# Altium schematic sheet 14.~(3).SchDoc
size 398 x 287 mm
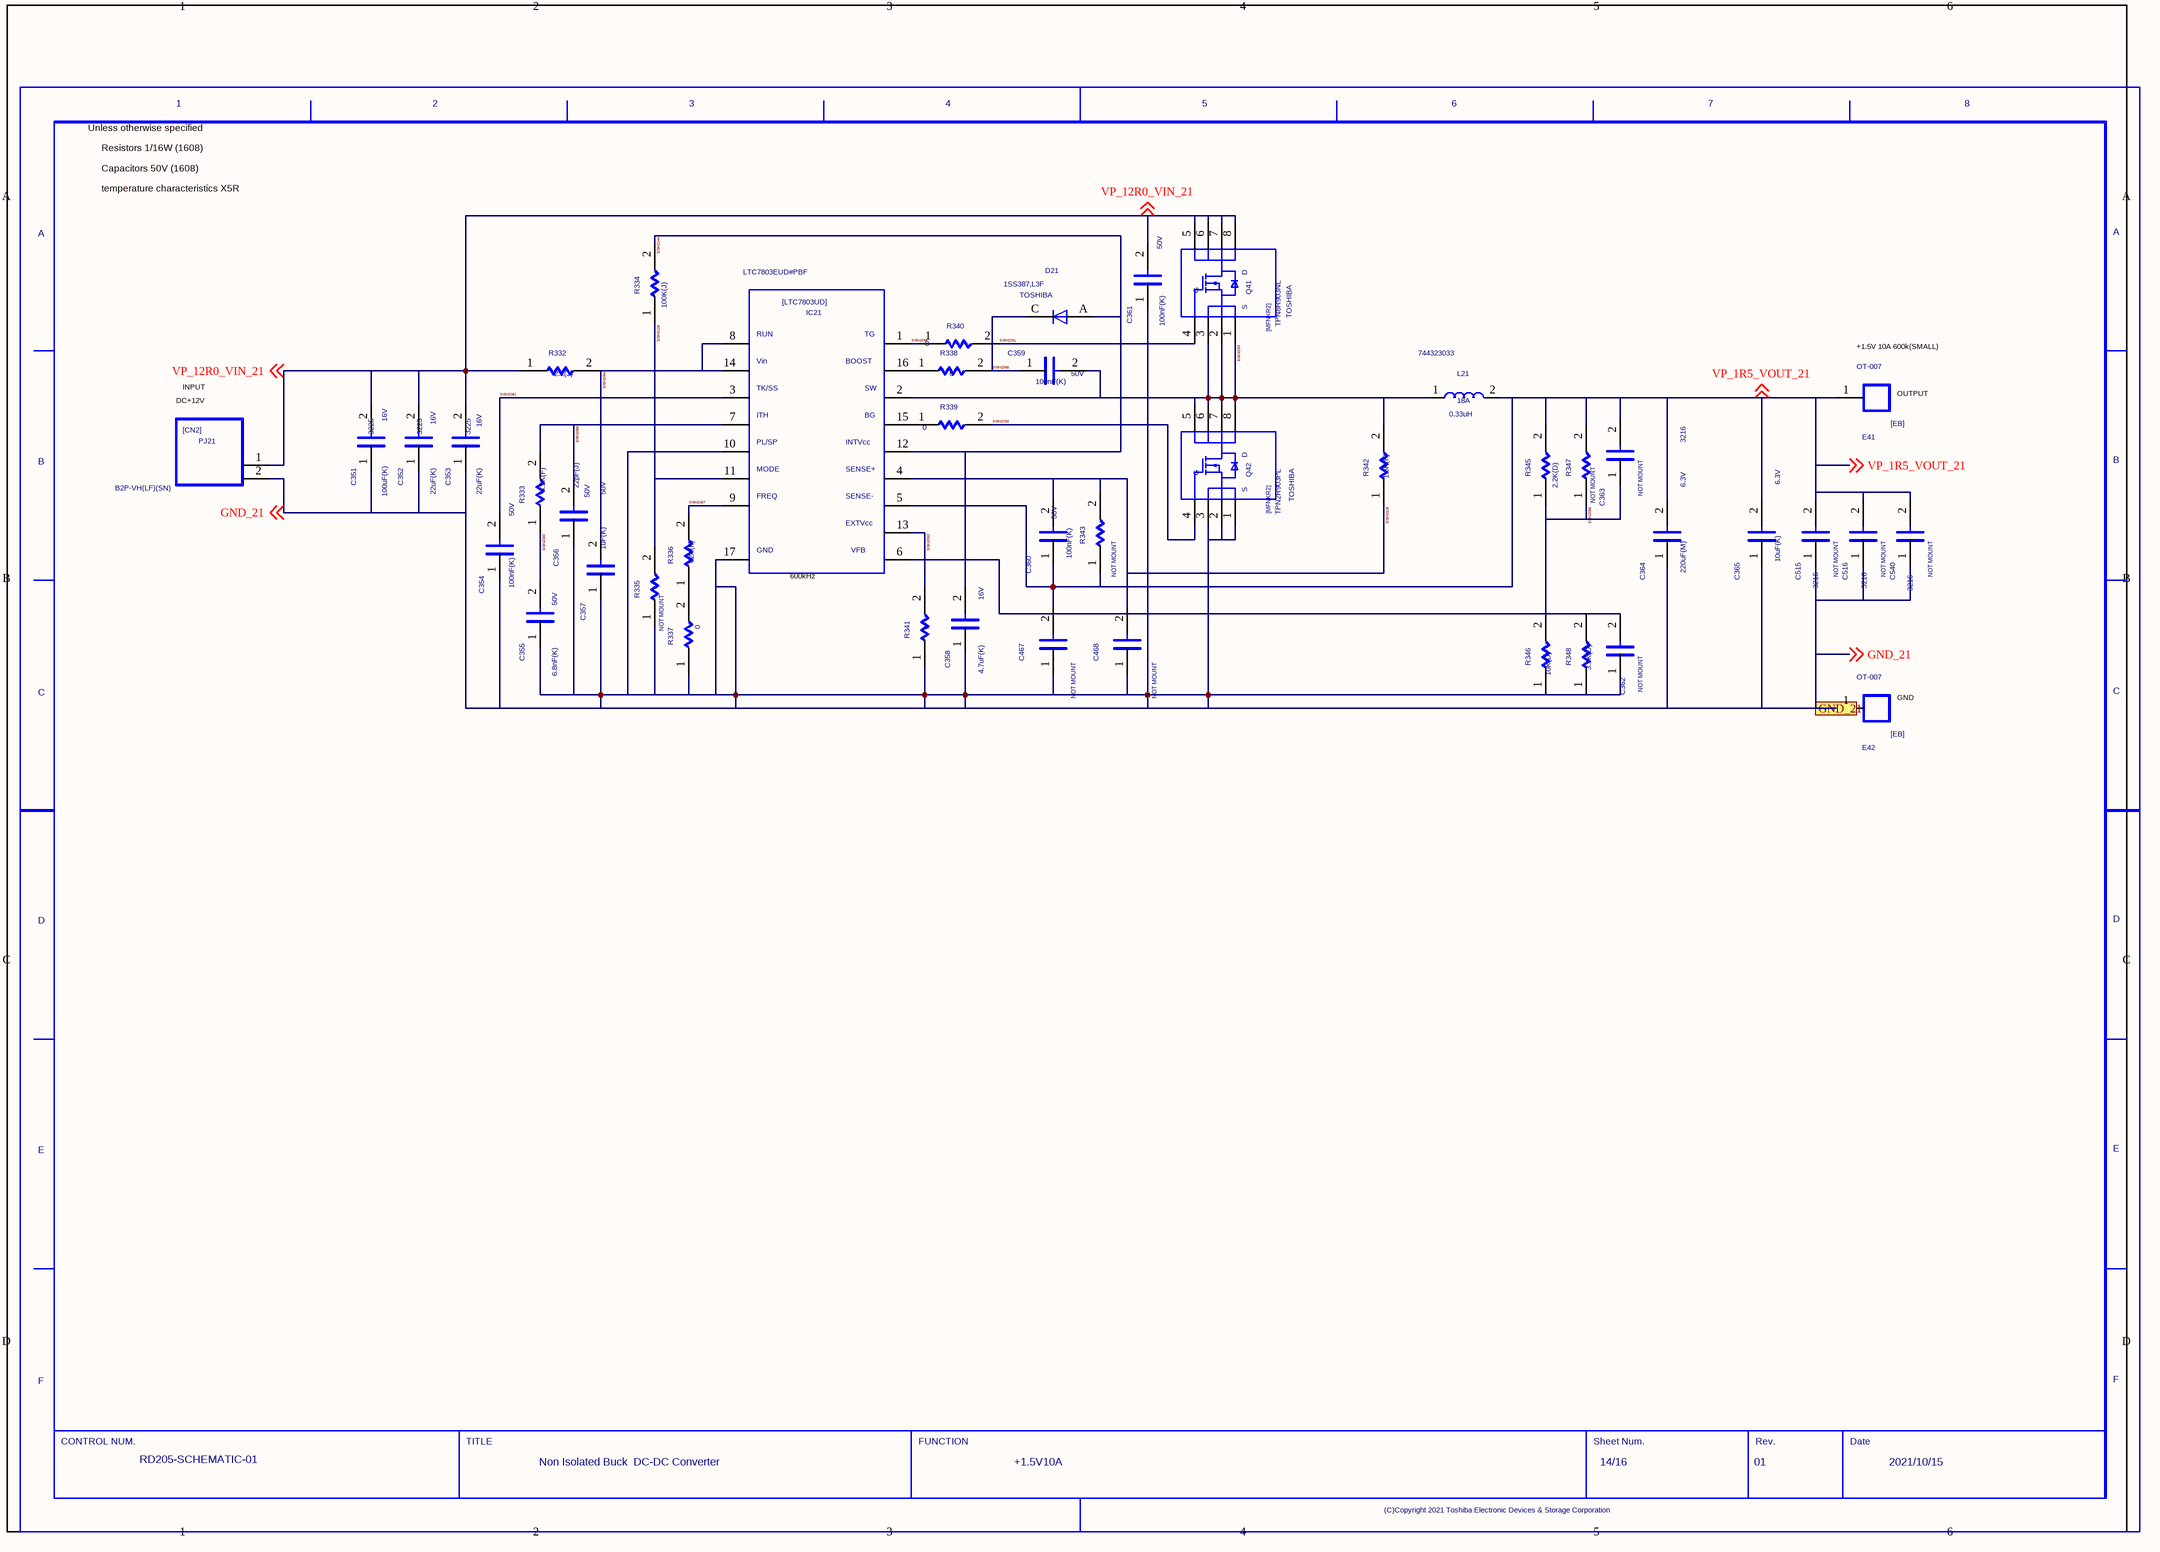
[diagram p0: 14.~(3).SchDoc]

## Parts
C351  SIZECODESMD: 3225  VAL2: 16V  VAL1: 100uF(K)  (hidden comment: C)
C352  SIZECODESMD: 3225  VAL2: 16V  VAL1: 22uF(K)  (hidden comment: C)
C353  SIZECODESMD: 3225  VAL2: 16V  VAL1: 22uF(K)  (hidden comment: C)
C354  VAL2: 50V  VAL1: 100nF(K)  (hidden comment: C)
C355  VAL2: 50V  VAL1: 6.8nF(K)  (hidden comment: C)
C356  VAL2: 50V  VAL1: 22pF(J)  (hidden comment: C)
C357  VAL2: 50V  VAL1: 1uF(K)  (hidden comment: C)
C358  VAL2: 16V  VAL1: 4.7uF(K)  (hidden comment: C)
C359  VAL2: 50V  VAL1: 100nF(K)  (hidden comment: C)
C360  VAL2: 50V  VAL1: 100nF(K)  (hidden comment: C)
C361  VAL2: 50V  VAL1: 100nF(K)  (hidden comment: C)
C362  NOTMOUNT: NOT MOUNT  (hidden comment: C)
C363  NOTMOUNT: NOT MOUNT  (hidden comment: C)
C364  SIZECODESMD: 3216  VAL2: 6.3V  VAL1: 220uF(M)  (hidden comment: C)
C365  VAL2: 6.3V  VAL1: 10uF(K)  (hidden comment: C)
C467  NOTMOUNT: NOT MOUNT  (hidden comment: C)
C468  NOTMOUNT: NOT MOUNT  (hidden comment: C)
C515  NOTMOUNT: NOT MOUNT  SIZECODESMD: 3216  (hidden comment: C)
C516  NOTMOUNT: NOT MOUNT  SIZECODESMD: 3216  (hidden comment: C)
C540  NOTMOUNT: NOT MOUNT  SIZECODESMD: 3216  (hidden comment: C)
D21  USERCOMPTEXT3: TOSHIBA  VAL3: 1SS387,L3F  (hidden comment: D)
E41  VAL3: OT-007  (hidden comment: EB)
E42  VAL3: OT-007  (hidden comment: EB)
IC21  VAL3: LTC7803EUD#PBF  (hidden comment: LTC7803UD)
L21  VAL3: 744323033  VAL2: 18A  VAL1: 0.33uH  (hidden comment: L)
PJ21  VAL3: B2P-VH(LF)(SN)  (hidden comment: CN2)
Q41  USERCOMPTEXT3: TOSHIBA  VAL3: TPN8R903NL  (hidden comment: MFNKR2)
Q42  USERCOMPTEXT3: TOSHIBA  VAL3: TPN2R903PL  (hidden comment: MFNKR2)
R332  VAL1: 2.2(J)  (hidden comment: R)
R333  VAL1: 4.3K(F)  (hidden comment: R)
R334  VAL1: 100K(J)  (hidden comment: R)
R335  NOTMOUNT: NOT MOUNT  (hidden comment: R)
R336  VAL1: 62K(F)  (hidden comment: R)
R337  VAL1: 0  (hidden comment: R)
R338  VAL1: 0  (hidden comment: R)
R339  VAL1: 0  (hidden comment: R)
R340  VAL1: 0  (hidden comment: R)
R341  VAL1: 0  (hidden comment: R)
R342  VAL1: 1.5K(F)  (hidden comment: R)
R343  NOTMOUNT: NOT MOUNT  (hidden comment: R)
R345  VAL1: 2.2K(D)  (hidden comment: R)
R346  VAL1: 10K(D)  (hidden comment: R)
R347  NOTMOUNT: NOT MOUNT  (hidden comment: R)
R348  VAL1: 3.3K(D)  (hidden comment: R)
U?  DATE: 2021/10/15  SHEETNUMBER: 14/16  TITLE: Non Isolated Buck / DC-DC Converter  REVISION: 01  DRAWINGNUMBER: RD205-SCHEMATIC-01  FUNCTION: +1.5V10A  (hidden comment: WAKU_DEF100)

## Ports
GND_21

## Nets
GND_21: C351.1 C352.1 C353.1 C354.1 C355.1 C356.1 C357.1 C358.1 C361.1 C362.1 C364.1 C365.1 C467.1 C468.1 C515.1 C516.1 C540.1 E42.1 IC21.10 IC21.17 PJ21.2 Q42.1 Q42.2 Q42.3 R335.1 R337.1 R341.1 R346.1 R348.1 ; off-sheet GND_21, port GND_21
SIGN2056: C362.2 C363.1 IC21.6 R345.1 R346.2 R347.1 R348.2
SIGN2058: C356.2 IC21.7 R333.2
SIGN2060: C355.2 R333.1
SIGN2061: C354.2 IC21.3
SIGN2063: IC21.13 R341.2
SIGN2064: C357.2 IC21.8 IC21.14 R332.2
SIGN2065: C359.1 D21.C R338.2
SIGN2066: IC21.1 R340.1
SIGN2067: IC21.9 R336.2
SIGN2125: IC21.11 R334.1 R335.2
SIGN2144: C358.2 D21.A IC21.12 R334.2
SIGN2291: Q41.4 R340.2
SIGN2292: Q42.4 R339.2
SIGN2293: C359.2 IC21.2 L21.1 Q41.1 Q41.2 Q41.3 Q42.5 Q42.6 Q42.7 Q42.8 R342.2
SIGN2318: C360.2 C468.2 IC21.4 R342.1 R343.2
VP_1R5_VOUT_21: C360.1 C363.2 C364.2 C365.2 C467.2 C515.2 C516.2 C540.2 E41.1 IC21.5 L21.2 R343.1 R345.2 R347.2 ; off-sheet VP_1R5_VOUT_21
VP_12R0_VIN_21: C351.2 C352.2 C353.2 C361.2 PJ21.1 Q41.5 Q41.6 Q41.7 Q41.8 R332.1 ; off-sheet VP_12R0_VIN_21
NetIC21_15: IC21.15 R339.1
NetIC21_16: IC21.16 R338.1
NetR336_1: R336.1 R337.2

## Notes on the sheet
- Unless otherwise specified
- Capacitors 50V (1608)
- Resistors 1/16W (1608)
- temperature characteristics X5R
- DC+12V
- INPUT
- (near E41) +1.5V 10A 600k(SMALL)
- (near E41) OUTPUT
- (near IC21) 600kHz
- (near E42) GND

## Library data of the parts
C351 = C: SQ_PART_MODEL: CON_100n; FNPARTSNAMEG: CHIP CERAMIC CAPACITOR (3225); USEINPARTSLIST: YES; OriginalSymbolOrigin: (2540,7620); MFSOLDERINGPROP: .; TEMPCHARACTERI2: B; MFFORMINGDIVP: KC; OUMECLASSIFICATION: セラミックコンデンサ; MFMOUNTSYMBOLP: 90; CDMASTERCADCELG: DC903A; PCODE: P03276001115; FNCLASSCODEG: P03-03; MAXGCOUNT: 1; RATEDVOLTAGE: 250; COMPONENTNAME: G36030160049; OUMEMAKER: KYC 京セラ; MFPACKAGEMETHOP: S; NOMINALCAPACITA: 100n; OUMEMAKERKATAMEI: CF32W5R104K250AT; CAPACITANCETOLE: K
C352 C353 = C: SQ_PART_MODEL: CON_22u; FNPARTSNAMEG: CHIP CERAMIC CAPACITOR (3225); USEINPARTSLIST: YES; OriginalSymbolOrigin: (2540,7620); MFSOLDERINGPROP: .; TEMPCHARACTERI2: B; MFFORMINGDIVP: KC; OUMECLASSIFICATION: セラミックコンデンサ; MFMOUNTSYMBOLP: 80; CDMASTERCADCELG: DC903A; PCODE: P03043035626; FNCLASSCODEG: P03-03; MAXGCOUNT: 1; RATEDVOLTAGE: 6.3; COMPONENTNAME: G36030119054; OUMEMAKER: TYD 太陽誘電; MFPACKAGEMETHOP: S; NOMINALCAPACITA: 22u; OUMEMAKERKATAMEI: JMK325BJ226KM-T; CAPACITANCETOLE: K
C354 C359 C361 = C: SQ_PART_MODEL: CON_100n; FNPARTSNAMEG: CHIP CERAMIC CAPACITOR (1608); USEINPARTSLIST: YES; OriginalSymbolOrigin: (2540,7620); MFSOLDERINGPROP: .; TEMPCHARACTERI2: B; MFFORMINGDIVP: KC; OUMECLASSIFICATION: セラミックコンデンサ; SIZECODESMD: 1608; MFMOUNTSYMBOLP: 80; CDMASTERCADCELG: C8100E; PCODE: P03B000000E4; FNCLASSCODEG: P03-03; MAXGCOUNT: 1; RATEDVOLTAGE: 16; COMPONENTNAME: GDM030000598; OUMEMAKER: MRT 村田製作所; MFPACKAGEMETHOP: S; NOMINALCAPACITA: 100n; OUMEMAKERKATAMEI: GRM188B11C104KA01C; CAPACITANCETOLE: K
C355 = C: SQ_PART_MODEL: CON_6.8n; FNPARTSNAMEG: CHIP CERAMIC CAPACITOR (1608); USEINPARTSLIST: YES; OriginalSymbolOrigin: (2540,7620); TOLERANCE: K; ASIMVALUE: 6.8N; MFSOLDERINGPROP: .; TEMPCHARACTERI2: B; MFFORMINGDIVP: KC; OUMECLASSIFICATION: セラミックコンデンサ; SIZECODESMD: 1608; MFMOUNTSYMBOLP: 80; CDMASTERCADCELG: C8100E; PCODE: P03039109225; FNCLASSCODEG: P03-03; MAXGCOUNT: 1; RATEDVOLTAGE: 50; COMPONENTNAME: G36030011440; OUMEMAKER: MRT 村田製作所; MFPACKAGEMETHOP: S; OUMEMAKERKATAMEI: GRM39B682K50PT
C356 = C: SQ_PART_MODEL: CON_22p; FNPARTSNAMEG: CHIP CERAMIC CAPACITOR (1608); USEINPARTSLIST: YES; OriginalSymbolOrigin: (2540,7620); TOLERANCE: J; ASIMVALUE: 22P; CDMASTERCADCELG: C8100E; MFSOLDERINGPROP: .; TEMPCHARACTERI2: CH; MFFORMINGDIVP: KC; OUMECLASSIFICATION: セラミックコンデンサ; SIZECODESMD: 1608; MFMOUNTSYMBOLP: 80; PCODE: P03039A02625; FNCLASSCODEG: P03-03; MAXGCOUNT: 1; RATEDVOLTAGE: 50; COMPONENTNAME: G36030011129; OUMEMAKER: TYD 太陽誘電; MFPACKAGEMETHOP: S; OUMEMAKERKATAMEI: UMK107CH220JZ-T
C357 = C: SQ_PART_MODEL: CON_1u; FNPARTSNAMEG: CHIP CERAMIC CAPACITOR (1608); USEINPARTSLIST: YES; OriginalSymbolOrigin: (2540,7620); MFSOLDERINGPROP: .; TEMPCHARACTERI2: B; MFFORMINGDIVP: KC; OUMECLASSIFICATION: セラミックコンデンサ; SIZECODESMD: 1608; MFMOUNTSYMBOLP: 80; CDMASTERCADCELG: C8100E; PCODE: P03039ACE122; FNCLASSCODEG: P03-03; MAXGCOUNT: 1; RATEDVOLTAGE: 6.3; COMPONENTNAME: G36030104159; OUMEMAKER: KYC 京セラ; MFPACKAGEMETHOP: S; NOMINALCAPACITA: 1u; OUMEMAKERKATAMEI: CM105B105K06ATN; CAPACITANCETOLE: K
C358 = C: SQ_PART_MODEL: CON_4.7u; FNPARTSNAMEG: CHIP CERAMIC CAPACITOR (1608); USEINPARTSLIST: YES; OriginalSymbolOrigin: (2540,7620); MFSOLDERINGPROP: .; TEMPCHARACTERI2: B; MFFORMINGDIVP: KC; OUMECLASSIFICATION: セラミックコンデンサ; SIZECODESMD: 1608; MFMOUNTSYMBOLP: 80; CDMASTERCADCELG: C8100E; PCODE: P03B000000MS; FNCLASSCODEG: P03-03; MAXGCOUNT: 1; RATEDVOLTAGE: 4; COMPONENTNAME: GDM030000053; OUMEMAKER: KYC 京セラ; MFPACKAGEMETHOP: S; NOMINALCAPACITA: 4.7u; OUMEMAKERKATAMEI: CM105B475M04AT; CAPACITANCETOLE: M
C360 = C: SQ_PART_MODEL: CON_100n; FNPARTSNAMEG: CHIP CERAMIC CAPACITOR (1608); USEINPARTSLIST: YES; OriginalSymbolOrigin: (2540,7620); MFSOLDERINGPROP: .; TEMPCHARACTERI2: B; MFFORMINGDIVP: KC; OUMECLASSIFICATION: セラミックコンデンサ; SIZECODESMD: 1608; MFMOUNTSYMBOLP: 80; CDMASTERCADCELG: C8100E; PCODE: P03B000000E4; FNCLASSCODEG: P03-03; MAXGCOUNT: 1; RATEDVOLTAGE: 16; COMPONENTNAME: GDM030001129; OUMEMAKER: MRT 村田製作所; MFPACKAGEMETHOP: S; NOMINALCAPACITA: 100n; OUMEMAKERKATAMEI: GRM188B11C104KA01C; CAPACITANCETOLE: K
C362 C363 = C: SQ_PART_MODEL: CON_100p; FNPARTSNAMEG: CHIP CERAMIC CAPACITOR (1608); USEINPARTSLIST: YES; OriginalSymbolOrigin: (2540,7620); TOLERANCE: J; ASIMVALUE: 100P; MFSOLDERINGPROP: .; TEMPCHARACTERI2: CH; MFFORMINGDIVP: KC; OUMECLASSIFICATION: セラミックコンデンサ; SIZECODESMD: 1608; MFMOUNTSYMBOLP: 80; CDMASTERCADCELG: C8100E; PCODE: P03039177125; FNCLASSCODEG: P03-03; MAXGCOUNT: 1; RATEDVOLTAGE: 50; COMPONENTNAME: G36030011365; OUMEMAKER: KYC 京セラ; MFPACKAGEMETHOP: S; OUMEMAKERKATAMEI: CM105CH101J50AT; VAL2: 50V; VAL1: 100pF(J)
C364 = C: SQ_PART_MODEL: CON_22u; FNPARTSNAMEG: CHIP CERAMIC CAPACITOR (3216); USEINPARTSLIST: YES; OriginalSymbolOrigin: (2540,7620); MFSOLDERINGPROP: .; TEMPCHARACTERI2: B; MFFORMINGDIVP: KC; OUMECLASSIFICATION: セラミックコンデンサ; MFMOUNTSYMBOLP: 80; CDMASTERCADCELG: DC901A; PCODE: P03B0000004V; FNCLASSCODEG: P03-03; MAXGCOUNT: 1; RATEDVOLTAGE: 6.3; COMPONENTNAME: GDM030000020; OUMEMAKER: KYC 京セラ; MFPACKAGEMETHOP: S; NOMINALCAPACITA: 22u; OUMEMAKERKATAMEI: CM316B226M06AT; CAPACITANCETOLE: M
C365 = C: SQ_PART_MODEL: CON_1u; FNPARTSNAMEG: CHIP CERAMIC CAPACITOR (1608); PARTCOMMENT: 代表セル<KC0008> がフットプリントに登録されていません。; USEINPARTSLIST: YES; OriginalSymbolOrigin: (2540,7620); MFSOLDERINGPROP: .; TEMPCHARACTERI2: B; MFPACKAGEMETHOP: S; MFFORMINGDIVP: KC; MFMOUNTSYMBOLP: 80; PCODE: P03B000000ZQ; OUMECLASSIFICATION: セラミックコンデンサ; SIZECODESMD: 1608; CDMASTERCADCELG: KC0008; FNCLASSCODEG: P03-03; MAXGCOUNT: 1; RATEDVOLTAGE: 6.3; COMPONENTNAME: GDM030000202; OUMEMAKER: MRT 村田製作所; NOMINALCAPACITA: 1u; OUMEMAKERKATAMEI: GRM185B10J105KE21D; CAPACITANCETOLE: K
C467 C468 = C: SQ_PART_MODEL: CON_220n; FNPARTSNAMEG: CHIP CERAMIC CAPACITOR (1608); PARTCOMMENT: 代表セル<KC0008> がフットプリントに登録されていません。; USEINPARTSLIST: YES; OriginalSymbolOrigin: (2540,7620); MFSOLDERINGPROP: .; TEMPCHARACTERI2: B; MFFORMINGDIVP: KC; OUMECLASSIFICATION: セラミックコンデンサ; SIZECODESMD: 1608; MFMOUNTSYMBOLP: 80; CDMASTERCADCELG: KC0008; PCODE: P03B000001L3; FNCLASSCODEG: P03-03; MAXGCOUNT: 1; RATEDVOLTAGE: 16; COMPONENTNAME: GDM030001129; OUMEMAKER: MRT 村田製作所; MFPACKAGEMETHOP: S; NOMINALCAPACITA: 220n; OUMEMAKERKATAMEI: GRM188B11C224KA01D; VAL2: 16V; VAL1: 220nF(K); CAPACITANCETOLE: K
C515 C516 C540 = C: SQ_PART_MODEL: CON_22u; FNPARTSNAMEG: CHIP CERAMIC CAPACITOR (3216); USEINPARTSLIST: YES; OriginalSymbolOrigin: (2540,7620); MFSOLDERINGPROP: .; TEMPCHARACTERI2: B; MFFORMINGDIVP: KC; OUMECLASSIFICATION: セラミックコンデンサ; MFMOUNTSYMBOLP: 80; CDMASTERCADCELG: DC901A; PCODE: P03B0000004V; FNCLASSCODEG: P03-03; MAXGCOUNT: 1; RATEDVOLTAGE: 6.3; COMPONENTNAME: GDM030000020; OUMEMAKER: KYC 京セラ; MFPACKAGEMETHOP: S; NOMINALCAPACITA: 22u; OUMEMAKERKATAMEI: CM316B226M06AT; VAL2: 6.3V; VAL1: 22uF(M); CAPACITANCETOLE: M
D21 = D: FNPARTSNAMEG: DIODE; USEINPARTSLIST: YES; PARTNAME: GDM420000143; SAVEAREA0: -565,-171,12979,8058; SAVECOUNT: 1; TIME: 14:49:55; UPDATEUSER: 19870035; UPDATETIME: 14:20:16; OriginalSymbolOrigin: (5080,5080); FORWARDVOLTAGEM: 0; MAXREVERSEVOLTA: 80; COMPONENTNAME: GDM420000143_package; MFSOLDERINGPROP: .; OUMEMAKER: TSB 東芝（ＹＰＳＳ）; QUADMODEL: dummymodel; MFPACKAGEMETHOP: S; MFFORMINGDIVP: MM; MOUNTINGFORMSMD: SMD; OUMECLASSIFICATION: 小信号ダイオード; OUMEMAKERKATAMEI: 1SS387(TPH3,F); CDMASTERCADCELG: D8101D; PCODE: P42B0000008E; FNCLASSCODEG: P42-01
E41 E42 = EB: FNPARTSNAMEG: TERMINAL; USEINPARTSLIST: YES; PARTNAME: 5P9L1232P001; OUMEPARTTYPE: TB; OriginalSymbolOrigin: (2540,12700); COMPONENTNAME: 5P9L1232P001_package; MAXGCOUNT: 1; MFSOLDERINGPROP: .; OUMEMAKER: オサダ; QUADMODEL: dummymodel; MFPACKAGEMETHOP: I; MFFORMINGDIVP: OD; OUMECLASSIFICATION: 端子台、端子板; CDMASTERCADCELG: DE0009; KIND: PBS; PCODE: P29045001117; TERMINALSTYLE: SC; FNCLASSCODEG: P29-01
IC21 = LTC7803UD: USEINPARTSLIST: YES; SAVECOUNT: 29; SAVEAREA0: -53177,0,89020,58420; TIME: 16:14:14; UPDATEUSER: q91866sr; UPDATETIME: 13:15:36; OriginalSymbolOrigin: (5080,55880); MAXGCOUNT: 1; COMPONENTNAME: LTC7803UD_LTC7803UD; OUMEMAKER: ANALOG DEVICES
L21 = L: USEINPARTSLIST: YES; PARTNAME: 7443310047; OriginalSymbolOrigin: (2540,5080); MAXGCOUNT: 1; COMPONENTNAME: L_L; OUMEMAKER: WURTH
PJ21 = CN2: FNPARTSNAMEG: 3.96PITCH NYLON CONNECTOR; USEINPARTSLIST: YES; PARTNAME: G36220114012; OUMEPARTTYPE: CN; OriginalSymbolOrigin: (2540,15240); MAXGCOUNT: 1; RATEDCURRENT: 7; COMPONENTNAME: G36220114012_package; MFSOLDERINGPROP: .; OUMEMAKER: JST 日本圧着端子製造; NUMBEROFCONTACT: 2; QUADMODEL: dummymodel; MFPACKAGEMETHOP: I; MFFORMINGDIVP: CU; CONTACTPITCH: 3.96m; OUMEMAKERKATAMEI: B2P-VH; CDMASTERCADCELG: DPJ514; PCODE: P22346001114; TERMINALSTYLE: PW; FNCLASSCODEG: P22-10
Q41 Q42 = MFNKR2: USEINPARTSLIST: YES; PARTNAME: TPN1R603PL; SAVEAREA0: -9199,-39,32138,22820; TIME: 18:57:44; UPDATEUSER: q91866sr; UPDATETIME: 12:36:02; SAVECOUNT: 10; OriginalSymbolOrigin: (5080,20320); MAXGCOUNT: 1; COMPONENTNAME: MFNKR2_MFNKR2
R332 = R: SQ_PART_MODEL: RES_2.2; FNPARTSNAMEG: CHIP RESISTOR (1608); USEINPARTSLIST: YES; OriginalSymbolOrigin: (5080,5080); TOLERANCE: J; ASIMVALUE: 2.2; MAXGCOUNT: 1; COMPONENTNAME: G36010011507; MFSOLDERINGPROP: .; OUMEMAKER: NAE 松下電子部品; MFPACKAGEMETHOP: S; MFFORMINGDIVP: KC; MOUNTINGFORMSMD: SMD; OUMECLASSIFICATION: 表面実装用固定抵抗器; MFMOUNTSYMBOLP: 80; POWERRATING: 63m; OUMEMAKERKATAMEI: ERJ3GEYJ2R2V; NUMBEROFELEMENT: 0; VAL2: 62.5mW; CDMASTERCADCELG: DR802R; PCODE: P01042157622; FNCLASSCODEG: P01-08
R333 = R: SQ_PART_MODEL: RES_4.3K; FNPARTSNAMEG: CHIP RESISTOR (1608); USEINPARTSLIST: YES; OriginalSymbolOrigin: (5080,5080); PCODE: P01042335624; MAXGCOUNT: 1; COMPONENTNAME: G5101105L102; MFSOLDERINGPROP: .; OUMEMAKER: NAE 松下電子部品; MFPACKAGEMETHOP: S; MFFORMINGDIVP: KC; MOUNTINGFORMSMD: SMD; OUMECLASSIFICATION: 表面実装用固定抵抗器; RESISTANCETOLER: F; MFMOUNTSYMBOLP: 80; POWERRATING: 63m; OUMEMAKERKATAMEI: ERJ3GEYF432V; NOMINALRESISTAN: 4.3K; NUMBEROFELEMENT: 0; VAL2: 62.5mW; CDMASTERCADCELG: DR802R; FNCLASSCODEG: P01-08
R334 = R: SQ_PART_MODEL: RES_100K; FNPARTSNAMEG: CHIP RESISTOR (1608); USEINPARTSLIST: YES; OriginalSymbolOrigin: (5080,5080); TOLERANCE: J; ASIMVALUE: 100K; MFSOLDERINGPROP: .; MFPACKAGEMETHOP: S; MFFORMINGDIVP: KC; MOUNTINGFORMSMD: SMD; MFMOUNTSYMBOLP: 80; NUMBEROFELEMENT: 0; PCODE: P01042047220; MAXGCOUNT: 1; COMPONENTNAME: G36010011057; OUMEMAKER: HDK 北陸電気工業; OUMECLASSIFICATION: 表面実装用固定抵抗器; POWERRATING: 63m; OUMEMAKERKATAMEI: CR1/16 104JV; VAL2: 62.5mW; CDMASTERCADCELG: DR802R; FNCLASSCODEG: P01-08
R335 = R: SQ_PART_MODEL: RES_10; FNPARTSNAMEG: CHIP RESISTOR (1608); USEINPARTSLIST: YES; OriginalSymbolOrigin: (5080,5080); TOLERANCE: F; ASIMVALUE: 10; MFSOLDERINGPROP: .; MFPACKAGEMETHOP: S; MFFORMINGDIVP: KC; MOUNTINGFORMSMD: SMD; MFMOUNTSYMBOLP: 80; NUMBEROFELEMENT: 0; PCODE: P01042036620; MAXGCOUNT: 1; COMPONENTNAME: G36010104063; OUMEMAKER: NAE 松下電子部品; OUMECLASSIFICATION: 表面実装用固定抵抗器; POWERRATING: 63m; OUMEMAKERKATAMEI: ERJ3GEYF100V; VAL2: 62.5mW; VAL1: 10(F); CDMASTERCADCELG: DR802R; FNCLASSCODEG: P01-08
R336 = R: SQ_PART_MODEL: RES_62K; FNPARTSNAMEG: CHIP RESISTOR (1608); USEINPARTSLIST: YES; OriginalSymbolOrigin: (5080,5080); MAXGCOUNT: 1; COMPONENTNAME: GDM010001037; MFSOLDERINGPROP: .; OUMEMAKER: NAE 松下電子部品; MFPACKAGEMETHOP: S; MFFORMINGDIVP: KC; MOUNTINGFORMSMD: SMD; OUMECLASSIFICATION: 表面実装用固定抵抗器; RESISTANCETOLER: F; MFMOUNTSYMBOLP: 80; POWERRATING: 63m; OUMEMAKERKATAMEI: ERJ3GEYF623V; NOMINALRESISTAN: 62K; NUMBEROFELEMENT: 0; VAL2: 62.5mW; CDMASTERCADCELG: DR802R; PCODE: P01042441622; FNCLASSCODEG: P01-08
R337 = R: SQ_PART_MODEL: RES_160K; FNPARTSNAMEG: CHIP RESISTOR (1608); USEINPARTSLIST: YES; OriginalSymbolOrigin: (5080,5080); MAXGCOUNT: 1; COMPONENTNAME: G51011061108; MFSOLDERINGPROP: .; OUMEMAKER: HDK 北陸電気工業; MFPACKAGEMETHOP: S; MFFORMINGDIVP: KC; MOUNTINGFORMSMD: SMD; OUMECLASSIFICATION: 表面実装用固定抵抗器; RESISTANCETOLER: F; MFMOUNTSYMBOLP: 80; POWERRATING: 63m; OUMEMAKERKATAMEI: CR1/16 164FV; NOMINALRESISTAN: 160K; VAL2: 62.5mW; CDMASTERCADCELG: DR802R; PCODE: P01042125225; FNCLASSCODEG: P01-08
R338 R341 = R: SQ_PART_MODEL: RES_10; FNPARTSNAMEG: CHIP RESISTOR (1608); USEINPARTSLIST: YES; OriginalSymbolOrigin: (5080,5080); TOLERANCE: F; ASIMVALUE: 10; MFSOLDERINGPROP: .; MFPACKAGEMETHOP: S; MFFORMINGDIVP: KC; MOUNTINGFORMSMD: SMD; MFMOUNTSYMBOLP: 80; PCODE: P01042036620; MAXGCOUNT: 1; COMPONENTNAME: G36010104063; OUMEMAKER: NAE 松下電子部品; OUMECLASSIFICATION: 表面実装用固定抵抗器; POWERRATING: 63m; OUMEMAKERKATAMEI: ERJ3GEYF100V; VAL2: 62.5mW; CDMASTERCADCELG: DR802R; FNCLASSCODEG: P01-08
R339 R340 = R: SQ_PART_MODEL: RES_10; FNPARTSNAMEG: CHIP RESISTOR (2012); USEINPARTSLIST: YES; OriginalSymbolOrigin: (5080,5080); MAXGCOUNT: 1; TOLERANCE: F; COMPONENTNAME: 5P9L1083P100; MFSOLDERINGPROP: .; OUMEMAKER: 北陸電気工業; MFPACKAGEMETHOP: S; MFFORMINGDIVP: KC; MOUNTINGFORMSMD: SMD; OUMECLASSIFICATION: 表面実装用固定抵抗器; ASIMVALUE: 10; MFMOUNTSYMBOLP: 90; POWERRATING: 100m; OUMEMAKERKATAMEI: CR1/10 100FV Pb(F); VAL2: 125mW; CDMASTERCADCELG: DR910A; PCODE: P01043091222; FNCLASSCODEG: P01-08
R342 = R: SQ_PART_MODEL: RES_1.5K; FNPARTSNAMEG: CHIP RESISTOR (1608); USEINPARTSLIST: YES; OriginalSymbolOrigin: (5080,5080); TOLERANCE: F; ASIMVALUE: 1.5K; MAXGCOUNT: 1; COMPONENTNAME: G36010104407; MFSOLDERINGPROP: .; OUMEMAKER: HDK 北陸電気工業; MFPACKAGEMETHOP: S; MFFORMINGDIVP: KC; MOUNTINGFORMSMD: SMD; OUMECLASSIFICATION: 表面実装用固定抵抗器; MFMOUNTSYMBOLP: 80; POWERRATING: 63m; OUMEMAKERKATAMEI: CR1/16 152FV; NUMBEROFELEMENT: 0; VAL2: 62.5mW; CDMASTERCADCELG: DR802R; PCODE: P01042512223; FNCLASSCODEG: P01-08
R343 = R: SQ_PART_MODEL: RES_8.2K; FNPARTSNAMEG: CHIP RESISTOR (1608); USEINPARTSLIST: YES; OriginalSymbolOrigin: (5080,5080); TOLERANCE: F; ASIMVALUE: 8.2K; MAXGCOUNT: 1; COMPONENTNAME: G36010027188; OUMEMAKER: KAM 釜屋電機; MOUNTINGFORMSMD: SMD; OUMECLASSIFICATION: 表面実装用固定抵抗器; POWERRATING: 63m; OUMEMAKERKATAMEI: RMC1/16-822FTP; CDMASTERCADCELG: DR802R; MFSOLDERINGPROP: .; MFPACKAGEMETHOP: S; MFFORMINGDIVP: KC; MFMOUNTSYMBOLP: 80; NUMBEROFELEMENT: 0; VAL2: 62.5mW; VAL1: 8.2K(F); PCODE: P01042507328; FNCLASSCODEG: P01-08
R345 = R: SQ_PART_MODEL: RES_2.2K; FNPARTSNAMEG: CHIP RESISTOR (1608); USEINPARTSLIST: YES; OriginalSymbolOrigin: (5080,5080); MAXGCOUNT: 1; COMPONENTNAME: G36010129332; MFSOLDERINGPROP: .; OUMEMAKER: NAE 松下電子部品; MFPACKAGEMETHOP: S; MFFORMINGDIVP: KC; MOUNTINGFORMSMD: SMD; OUMECLASSIFICATION: 表面実装用固定抵抗器; RESISTANCETOLER: D; MFMOUNTSYMBOLP: 80; POWERRATING: 63m; OUMEMAKERKATAMEI: ERJ3RBD222V; NOMINALRESISTAN: 2.2K; NUMBEROFELEMENT: 0; VAL2: 62.5mW; CDMASTERCADCELG: DR802R; PCODE: P01119035112; FNCLASSCODEG: P01-08
R346 = R: ICX_PART_MODEL: RES_10K; FNPARTSNAMEG: CHIP RESISTOR (1608); OriginalSymbolOrigin: (5080,5080); FNCLASSCODEG: P01-08; PCODE: P01117053118; CDMASTERCADCELG: DR802R; USEWITHSCHEMA: YES; VAL2: 62.5mW; NUMBEROFELEMENT: 0; NOMINALRESISTAN: 10K; OUMEMAKERKATAMEI: RK73G1JTD103D; POWERRATING: 63m; MFMOUNTSYMBOLP: 80; RESISTANCETOLER: D; FUNCTION: G36010129493; OUMECLASSIFICATION: 表面実装用固定抵抗器; MOUNTINGFORMSMD: SMD; MFFORMINGDIVP: KC; MFPACKAGEMETHOP: S; OUMEMAKER: KOA ＫＯＡ; MFSOLDERINGPROP: .; MAXGCOUNT: 1
R347 = R: SQ_PART_MODEL: RES_3.3K; FNPARTSNAMEG: CHIP RESISTOR (1608); USEINPARTSLIST: YES; OriginalSymbolOrigin: (5080,5080); TOLERANCE: F; ASIMVALUE: 3.3K; MAXGCOUNT: 1; COMPONENTNAME: G36010027027; MFSOLDERINGPROP: .; OUMEMAKER: ROH ロー・; MFPACKAGEMETHOP: S; MFFORMINGDIVP: KC; MOUNTINGFORMSMD: SMD; OUMECLASSIFICATION: 表面実装用固定抵抗器; MFMOUNTSYMBOLP: 80; POWERRATING: 63m; OUMEMAKERKATAMEI: MCR03EZPFX3301; NUMBEROFELEMENT: 0; VAL2: 62.5mW; VAL1: 3.3K(F); CDMASTERCADCELG: DR802R; PCODE: P01042250729; FNCLASSCODEG: P01-08
R348 = R: ICX_PART_MODEL: RES_3.3K; FNPARTSNAMEG: CHIP RESISTOR (1608); OriginalSymbolOrigin: (5080,5080); FNCLASSCODEG: P01-08; PCODE: P01117041115; CDMASTERCADCELG: DR802R; USEWITHSCHEMA: YES; VAL2: 62.5mW; NUMBEROFELEMENT: 0; NOMINALRESISTAN: 3.3K; OUMEMAKERKATAMEI: RK73G1JTD332D; POWERRATING: 63m; MFMOUNTSYMBOLP: 80; RESISTANCETOLER: D; FUNCTION: G36010129370; OUMECLASSIFICATION: 表面実装用固定抵抗器; MOUNTINGFORMSMD: SMD; MFFORMINGDIVP: KC; MFPACKAGEMETHOP: S; OUMEMAKER: KOA ＫＯＡ; MFSOLDERINGPROP: .; MAXGCOUNT: 1
U? = WAKU_DEF100: PLOTTIME: HH:MM; SAVEAREA0: 330961,54,387907,31546; TIME: 19:23:07; UPDATEUSER: t5459927; UPDATETIME: 15:33:42; SAVECOUNT: 6; OriginalSymbolOrigin: (10160,284480); DESIGNED: ***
